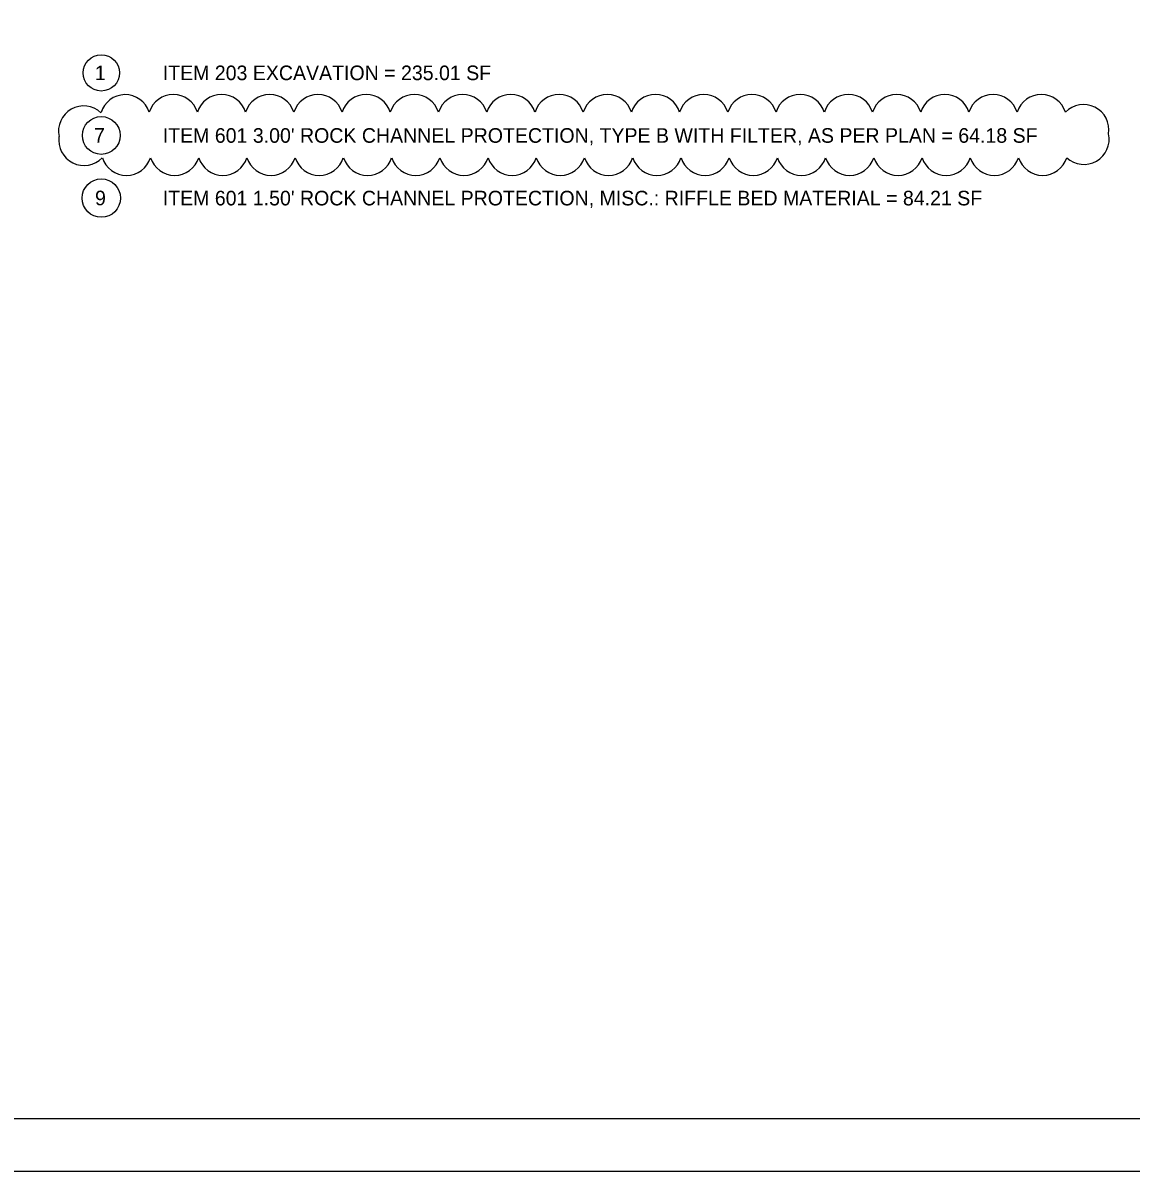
# Model space of a CAD drawing. Extents: x -31.8 to 34, y 0 to 22.
# Drawn here: x 13.01 to 23.63, y 0 to 11 of the extents above; entities that cross this region are included whole.
import ezdxf

# ---------------------------------------------------------------- set-up
doc = ezdxf.new("R2010")
doc.units = 0
for name, color, linetype in [('CS-ALGN-TEXT', 7, 'Continuous'), ('CS-ANNO', 7, 'Continuous'), ('CS-ANNO-MATC', 7, 'Continuous'), ('CS-ANNO-MATC-TEXT', 7, 'Continuous')]:
    doc.layers.add(name, color=color, linetype=linetype)

msp = doc.modelspace()

# ---------------------------------------------------------------- linework, layer by layer
at = {"layer": 'CS-ALGN-TEXT'}
for centre, start, end in [((13.992, 10.071), 18.2204, 163.2204), ((14.453, 10.073), 17.5, 162.5), ((14.915, 10.073), 17.5, 162.5), ((15.377, 10.073), 17.5, 162.5), ((15.84, 10.073), 17.5, 162.5), ((16.302, 10.073), 17.5, 162.5), ((16.764, 10.073), 17.5, 162.5), ((17.226, 10.073), 17.5, 162.5), ((17.688, 10.073), 17.5, 162.5), ((18.151, 10.073), 17.5, 162.5), ((18.613, 10.073), 17.5, 162.5), ((19.075, 10.073), 17.5, 162.5), ((19.537, 10.073), 17.5, 162.5), ((19.999, 10.073), 17.5, 162.5), ((20.461, 10.073), 17.5, 162.5), ((20.924, 10.073), 17.5, 162.5), ((21.386, 10.073), 17.5, 162.5), ((21.848, 10.073), 17.5, 162.5), ((22.31, 10.073), 17.5, 162.5), ((22.772, 10.073), 17.3148, 162.3148), ((13.595, 9.963), 47.0754, 192.0754), ((23.178, 9.976), 350.9393, 135.9393), ((13.597, 9.876), 171.3919, 316.3919), ((23.181, 9.887), 227.2483, 12.2483), ((14.004, 9.782), 197.5, 342.5), ((14.466, 9.782), 197.5, 342.5), ((14.928, 9.782), 197.5, 342.5), ((15.39, 9.782), 197.5, 342.5), ((15.852, 9.782), 197.5, 342.5), ((16.315, 9.782), 197.5, 342.5), ((16.777, 9.782), 197.5, 342.5), ((17.239, 9.782), 197.5, 342.5), ((17.701, 9.782), 197.5, 342.5), ((18.163, 9.782), 197.5, 342.5), ((18.625, 9.782), 197.5, 342.5), ((19.088, 9.782), 197.5, 342.5), ((19.55, 9.782), 197.5, 342.5), ((20.012, 9.782), 197.5, 342.5), ((20.474, 9.782), 197.5, 342.5), ((20.936, 9.782), 197.5, 342.5), ((21.399, 9.782), 197.5, 342.5), ((21.861, 9.782), 197.5, 342.5), ((22.323, 9.782), 197.5, 342.5), ((22.785, 9.782), 197.5, 342.5)]:
    msp.add_arc(centre, 0.242, start, end, dxfattribs=at)
at = {"layer": 'CS-ANNO'}
msp.add_lwpolyline([(0, 0), (34, 0), (34, 22), (0, 22)], close=True, dxfattribs=at)
at = {"layer": 'CS-ANNO-MATC'}
msp.add_lwpolyline([(1.5, 21.5), (33.5, 21.5), (33.5, 0.5), (1.5, 0.5)], close=True, dxfattribs=at)
at = {"layer": 'CS-ANNO-MATC-TEXT'}
for centre, radius in [((13.763, 10.522), 0.174), ((13.763, 9.922), 0.181), ((13.763, 9.322), 0.184)]:
    msp.add_circle(centre, radius, dxfattribs=at)

# ---------------------------------------------------------------- texts
for s, p in [('1', (13.702, 10.452)), ('ITEM 203 EXCAVATION = 235.01 SF', (14.352, 10.452)), ('7', (13.693, 9.853)), ("ITEM 601 3.00' ROCK CHANNEL PROTECTION, TYPE B WITH FILTER, AS PER PLAN = 64.18 SF", (14.352, 9.852)), ('9', (13.703, 9.253)), ("ITEM 601 1.50' ROCK CHANNEL PROTECTION, MISC.: RIFFLE BED MATERIAL = 84.21 SF", (14.352, 9.252))]:
    msp.add_text(s, height=0.14, dxfattribs=at).set_placement(p)

doc.saveas('drawing.dxf')
